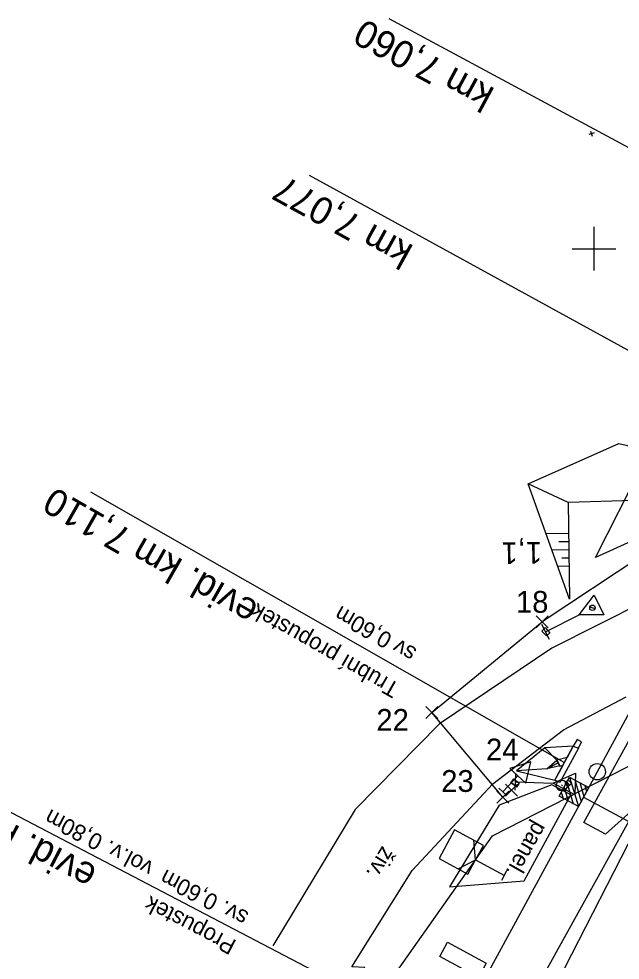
# Model space of a CAD drawing. Extents: x -795094 to -794639, y -1135368 to -1134681.
# Drawn here: x -794952.7 to -794897.6, y -1135065.2 to -1134978.9 of the extents above; entities that cross this region are included whole.
import ezdxf

# ---------------------------------------------------------------- set-up
doc = ezdxf.new("R2010")
doc.units = 0
for name, color, linetype in [('0381KM005-009P - Vrstva 1', 7, 'Continuous'), ('0381KM005-009P - Vrstva 12', 7, 'Continuous'), ('0381KM005-009P - Vrstva 16', 7, 'Continuous'), ('0381KM005-009P - Vrstva 17', 7, 'Continuous'), ('0381KM005-009P - Vrstva 19', 7, 'Continuous'), ('0381KM005-009P - Vrstva 28', 7, 'Continuous'), ('0381KM005-009P - Vrstva 3', 7, 'Continuous'), ('0381KM005-009P - Vrstva 33', 7, 'Continuous'), ('0381KM005-009P - Vrstva 4', 7, 'Continuous'), ('0381KM005-009P - Vrstva 48', 7, 'Continuous'), ('0381KM005-009P - Vrstva 49', 7, 'Continuous'), ('0381KM005-009P - Vrstva 51', 7, 'Continuous'), ('0381KM005-009P - Vrstva 6', 7, 'Continuous'), ('0381KM005-009P - Vrstva 7', 7, 'Continuous'), ('Default', 7, 'Continuous'), ('hran DP - hran DP', 7, 'Continuous'), ('krizky_1000 - Vrstva 1', 7, 'Continuous'), ('PSR_C2_1_Lomove_body_Strunkovice - Vrstva 60', 7, 'Continuous'), ('PSR_C2_1_trasa_Strunkovice - Kabelová trasa', 7, 'Continuous')]:
    doc.layers.add(name, color=color, linetype=linetype)

msp = doc.modelspace()

# ---------------------------------------------------------------- linework, layer by layer
at = {"layer": '0381KM005-009P - Vrstva 1'}
msp.add_lwpolyline([(-794888.877, -1135027.929), (-794896.922, -1135042.829), (-794900.945, -1135050.279), (-794913.191, -1135072.813), (-794931.084, -1135105.636), (-794935.694, -1135114.258)], dxfattribs=at)
at = {"layer": '0381KM005-009P - Vrstva 12'}
for p, q in [((-794907.349, -1135048.621), (-794907.346, -1135048.618)), ((-794907.596, -1135048.969), (-794907.584, -1135048.954)), ((-794907.089, -1135049.342), (-794907.105, -1135049.362)), ((-794906.838, -1135049.006), (-794906.837, -1135049.005))]:
    msp.add_line(p, q, dxfattribs=at)
for points in [[(-794904.34, -1135035.494), (-794904.782, -1135035.054), (-794904.464, -1135034.747), (-794904.043, -1135035.232), (-794904.34, -1135035.494)], [(-794907.596, -1135048.969), (-794907.349, -1135048.621), (-794906.838, -1135049.006), (-794907.089, -1135049.342), (-794907.596, -1135048.969)], [(-794907.584, -1135048.954), (-794907.346, -1135048.618), (-794906.837, -1135049.005), (-794907.105, -1135049.362), (-794907.584, -1135048.954)]]:
    msp.add_lwpolyline(points, dxfattribs=at)
at = {"layer": '0381KM005-009P - Vrstva 16'}
for points in [[(-794898.942, -1135053.674), (-794900.909, -1135052.62), (-794895.749, -1135043.22), (-794889.776, -1135038.979), (-794883.313, -1135039.729)], [(-794906.385, -1135057.965), (-794902.124, -1135050.064), (-794903.853, -1135049.172), (-794908.682, -1135051.013), (-794913.246, -1135058.523)]]:
    msp.add_lwpolyline(points, close=True, dxfattribs=at)
at = {"layer": '0381KM005-009P - Vrstva 17'}
msp.add_lwpolyline([(-794906.485, -1135078.852), (-794910.336, -1135076.942), (-794896.762, -1135052.473), (-794877.418, -1135038.884)], dxfattribs=at)
at = {"layer": '0381KM005-009P - Vrstva 19'}
for p, q in [((-794902.709, -1135047.123), (-794946.118, -1135022.337)), ((-794901.409, -1135045.784), (-794901.142, -1135045.228)), ((-794916.002, -1135071.262), (-794961.469, -1135047.516)), ((-794903.293, -1135047.157), (-794904.324, -1135047.684))]:
    msp.add_line(p, q, dxfattribs=at)
for points in [[(-794901.142, -1135045.228), (-794901.54, -1135045.015), (-794901.887, -1135045.598)], [(-794903.57, -1135048.718), (-794902.852, -1135047.403), (-794902.851, -1135047.401), (-794902.439, -1135046.654), (-794902.44, -1135046.655), (-794901.887, -1135045.598)], [(-794903.111, -1135047.406), (-794904.324, -1135047.684), (-794903.406, -1135046.893)]]:
    msp.add_lwpolyline(points, dxfattribs=at)
msp.add_lwpolyline([(-794903.128, -1135048.931), (-794903.57, -1135048.718), (-794901.887, -1135045.598), (-794901.409, -1135045.784)], close=True, dxfattribs=at)
msp.add_ellipse((-794903.262, -1135047.167), major_axis=(0.173, -0.304), ratio=0.062911, start_param=2.649673, end_param=6.913725, dxfattribs=at)
at = {"layer": '0381KM005-009P - Vrstva 28'}
msp.add_line((-794902.921, -1135049.174), (-794902.969, -1135049.262), dxfattribs=at)
msp.add_circle((-794902.945, -1135049.218), 0.5, dxfattribs=at)
at = {"layer": '0381KM005-009P - Vrstva 3'}
for p, q in [((-794882.938, -1135016.954), (-794926.069, -1134993.289)), ((-794902.225, -1135048.446), (-794901.422, -1135051.158)), ((-794901.759, -1135048.699), (-794901.169, -1135050.692)), ((-794902.732, -1135049.378), (-794902.355, -1135050.651)), ((-794902.478, -1135048.911), (-794901.888, -1135050.905)), ((-794901.293, -1135048.952), (-794900.916, -1135050.225)), ((-794900.827, -1135049.205), (-794900.663, -1135049.76)), ((-794902.985, -1135049.844), (-794902.82, -1135050.398)), ((-794900.945, -1135050.279), (-794850.198, -1135077.723))]:
    msp.add_line(p, q, dxfattribs=at)
msp.add_lwpolyline([(-794900.468, -1135049.4), (-794901.422, -1135051.158), (-794903.18, -1135050.203), (-794902.225, -1135048.446)], close=True, dxfattribs=at)
at = {"layer": '0381KM005-009P - Vrstva 33'}
msp.add_lwpolyline([(-794909.874, -1135065.516), (-794910.585, -1135066.824), (-794914.126, -1135064.901), (-794913.415, -1135063.593)], close=True, dxfattribs=at)
at = {"layer": '0381KM005-009P - Vrstva 4'}
for p, q in [((-794900.361, -1135032.842), (-794899.898, -1135033)), ((-794904.789, -1135034.425), (-794904.095, -1135035.817)), ((-794907.175, -1135048.108), (-794907.233, -1135049.662)), ((-794902.53, -1135048.837), (-794902.199, -1135049.198))]:
    msp.add_line(p, q, dxfattribs=at)
for points in [[(-794904.442, -1135035.121), (-794901.335, -1135033.561), (-794899.985, -1135031.778), (-794899.083, -1135033.561), (-794901.335, -1135033.561)], [(-794907.204, -1135048.885), (-794903.729, -1135049.002), (-794901.691, -1135048.084), (-794901.752, -1135050.081), (-794903.729, -1135049.002)]]:
    msp.add_lwpolyline(points, dxfattribs=at)
for centre in [(-794900.13, -1135032.922), (-794902.365, -1135049.018)]:
    msp.add_circle(centre, 0.248, dxfattribs=at)
at = {"layer": '0381KM005-009P - Vrstva 48'}
for p, q in [((-794902.332, -1135026.112), (-794904.398, -1135026.141)), ((-794902.322, -1135026.862), (-794903.226, -1135026.875)), ((-794902.311, -1135027.612), (-794903.864, -1135027.634)), ((-794902.301, -1135028.362), (-794902.949, -1135028.371)), ((-794902.291, -1135029.112), (-794903.33, -1135029.126))]:
    msp.add_line(p, q, dxfattribs=at)
at = {"layer": '0381KM005-009P - Vrstva 49'}
for p, q in [((-794900.297, -1134989.21), (-794900.153, -1134989.69)), ((-794899.985, -1134989.378), (-794900.465, -1134989.522)), ((-794902.371, -1135023.27), (-794906.037, -1135021.561)), ((-794904.51, -1135045.761), (-794903.406, -1135046.893)), ((-794901.887, -1135045.598), (-794902.44, -1135046.655)), ((-794904.324, -1135047.684), (-794903.406, -1135046.893)), ((-794903.57, -1135048.718), (-794902.852, -1135047.403))]:
    msp.add_line(p, q, dxfattribs=at)
for points in [[(-794902.249, -1135032.148), (-794906.037, -1135021.561), (-794897.72, -1135017.851), (-794890.171, -1135019.586)], [(-794890.343, -1135022.912), (-794902.371, -1135023.27), (-794902.249, -1135032.148)], [(-794901.887, -1135045.598), (-794904.51, -1135045.761), (-794907.099, -1135047.877), (-794903.57, -1135048.718)], [(-794902.44, -1135046.655), (-794903.406, -1135046.893), (-794903.111, -1135047.406), (-794902.852, -1135047.403)], [(-794903.111, -1135047.406), (-794904.324, -1135047.684), (-794907.099, -1135047.877)]]:
    msp.add_lwpolyline(points, dxfattribs=at)
at = {"layer": '0381KM005-009P - Vrstva 51'}
msp.add_line((-794908.701, -1135049.455), (-794907.969, -1135050.137), dxfattribs=at)
for points in [[(-794891.1, -1135030.195), (-794903.856, -1135036.615), (-794914.152, -1135043.554), (-794921.867, -1135051.409), (-794929.42, -1135063.919)], [(-794944.393, -1135111.84), (-794941.444, -1135105.511), (-794923.048, -1135070.462), (-794920.984, -1135065.893), (-794920.984, -1135065.893), (-794922.17, -1135065.853), (-794916.653, -1135056.999), (-794909.253, -1135049.068), (-794902.794, -1135044.104), (-794897.036, -1135041.091)], [(-794908.335, -1135049.796), (-794906.971, -1135048.334), (-794906.239, -1135049.016), (-794905.777, -1135047.054), (-794907.702, -1135047.651), (-794906.971, -1135048.334)]]:
    msp.add_lwpolyline(points, dxfattribs=at)
at = {"layer": '0381KM005-009P - Vrstva 6'}
msp.add_line((-794877.804, -1135000.976), (-794918.759, -1134978.921), dxfattribs=at)
at = {"layer": '0381KM005-009P - Vrstva 7'}
for p, q in [((-794910.84, -1135056.026), (-794908.204, -1135057.458)), ((-794908.443, -1135057.897), (-794907.965, -1135057.019))]:
    msp.add_line(p, q, dxfattribs=at)
for points in [[(-794910.84, -1135056.026), (-794910.124, -1135054.708), (-794912.76, -1135053.276), (-794914.192, -1135055.912), (-794911.556, -1135057.344), (-794910.84, -1135056.026)], [(-794912.437, -1135056.866), (-794910.84, -1135056.026), (-794911.005, -1135054.23)]]:
    msp.add_lwpolyline(points, dxfattribs=at)
msp.add_circle((-794899.687, -1135047.955), 0.75, dxfattribs=at)
at = {"layer": 'hran DP - hran DP'}
for p, q in [((-794899.86, -1135028.32), (-794880.53, -1134990.11)), ((-794874.12, -1135016.68), (-794899.86, -1135028.32)), ((-794909.29, -1135053.85), (-794891.95, -1135044.96)), ((-794891.95, -1135044.96), (-794908.62, -1135077.55)), ((-794917.84, -1135065.96), (-794909.29, -1135053.85))]:
    msp.add_line(p, q, dxfattribs=at)
at = {"layer": 'krizky_1000 - Vrstva 1'}
for points in [[(-794900, -1134998), (-794900, -1135002)], [(-794902, -1135000), (-794898, -1135000)]]:
    msp.add_lwpolyline(points, dxfattribs=at)
at = {"layer": 'PSR_C2_1_Lomove_body_Strunkovice - Vrstva 60'}
for p, q in [((-794905.302, -1135034.777), (-794904.202, -1135033.677)), ((-794904.202, -1135034.777), (-794905.302, -1135033.677)), ((-794915.41, -1135043.063), (-794914.31, -1135041.963)), ((-794914.31, -1135043.063), (-794915.41, -1135041.963)), ((-794908.104, -1135050.204), (-794907.004, -1135049.104)), ((-794907.004, -1135050.204), (-794908.104, -1135049.104)), ((-794908.883, -1135050.841), (-794907.783, -1135049.741)), ((-794907.783, -1135050.841), (-794908.883, -1135049.741))]:
    msp.add_line(p, q, dxfattribs=at)
at = {"layer": 'PSR_C2_1_trasa_Strunkovice - Kabelová trasa'}
msp.add_line((-794890.603, -1135024.815), (-794904.752, -1135034.227), dxfattribs=at)
msp.add_lwpolyline([(-794907.554, -1135049.654), (-794908.333, -1135050.291), (-794914.86, -1135042.513), (-794904.752, -1135034.227)], dxfattribs=at)

# ---------------------------------------------------------------- texts
at = {"layer": '0381KM005-009P - Vrstva 16'}
msp.add_text('panel.', height=1.5, rotation=240.37584, dxfattribs=at).set_placement((-794905.431, -1135052.376))
at = {"layer": '0381KM005-009P - Vrstva 19'}
for s, height, rotation, p in [('evid. km 7,110', 2.5, 150.27458, (-794930.601, -1135032.557)), ('Trubní propustek', 1.5, 150.27458, (-794917.695, -1135039.959)), ('sv 0,60m', 1.5, 150.27458, (-794916.143, -1135036.714)), ('evid. km 7,140', 2.5, 152.42364, (-794945.404, -1135056.76)), ('sv. 0,60m  vol.v. 0,80m', 1.5, 152.42364, (-794931.54, -1135060.881)), ('Propustek', 1.5, 152.42364, (-794932.666, -1135063.476))]:
    msp.add_text(s, height=height, rotation=rotation, dxfattribs=at).set_placement(p)
at = {"layer": '0381KM005-009P - Vrstva 3'}
msp.add_text('km 7,077', height=2.5, rotation=151.24674, dxfattribs=at).set_placement((-794916.408, -1134999.776))
at = {"layer": '0381KM005-009P - Vrstva 48'}
msp.add_text('1,1', height=2, rotation=180.7873, dxfattribs=at).set_placement((-794904.758, -1135026.879))
at = {"layer": '0381KM005-009P - Vrstva 51'}
msp.add_text('živ.', height=1.5, rotation=238.87823, dxfattribs=at).set_placement((-794919.381, -1135054.686))
at = {"layer": '0381KM005-009P - Vrstva 6'}
msp.add_text('km 7,060', height=2.5, rotation=151.69608, dxfattribs=at).set_placement((-794908.965, -1134985.366))
at = {"layer": 'Default'}
for s, p in [('18', (-794907.14, -1135033.381)), ('22', (-794919.936, -1135044.206)), ('24', (-794909.885, -1135046.923)), ('23', (-794913.991, -1135049.807))]:
    msp.add_text(s, height=2, dxfattribs=at).set_placement(p)

doc.saveas('drawing.dxf')
